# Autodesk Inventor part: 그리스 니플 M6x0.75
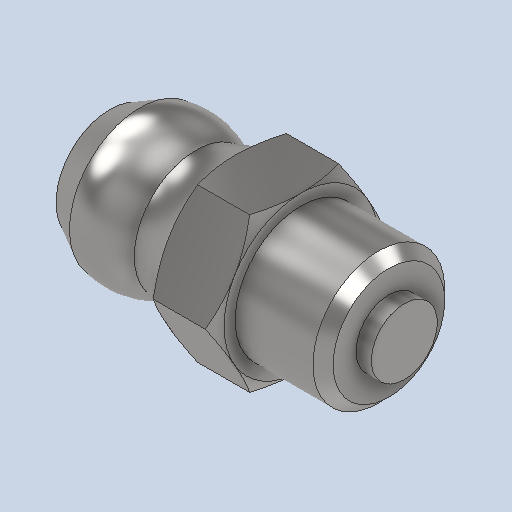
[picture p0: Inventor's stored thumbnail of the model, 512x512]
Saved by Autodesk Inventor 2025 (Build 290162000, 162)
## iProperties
Created: 2026-03
Part Number: 그리스 니플 M6x0.75
Material: 강철, 연강
Description: 윤활 니플, 원추 유형 A
Document SubType Name: Modeling
Designer: KDI
Density: 7.85 g/cm^3
Appearance: 기본값
Author: jhkim
Sending System: Autodesk Inventor 2026
Preprocessor: ST-DEVELOPER v20.1
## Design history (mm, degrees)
feature "Solid1"
node "솔리드1"
